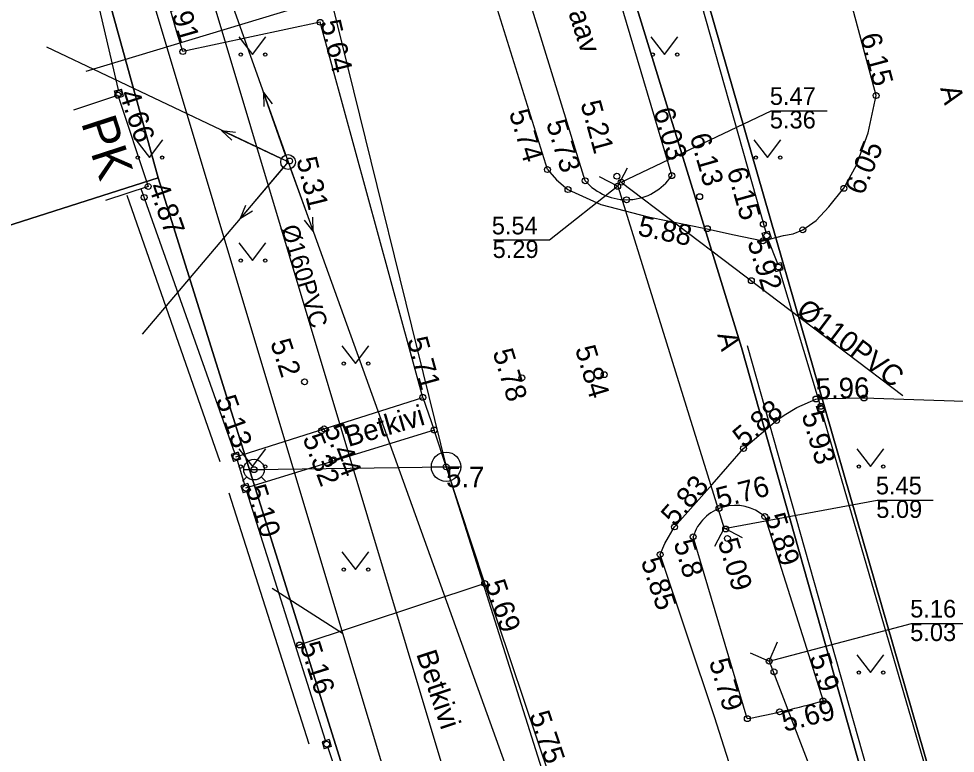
# Model space of a CAD drawing. Extents: x 473307 to 473719, y 6532843 to 6533381.
# Drawn here: x 473371.32 to 473403.15, y 6533155.23 to 6533180.18 of the extents above; entities that cross this region are included whole.
import ezdxf

# ---------------------------------------------------------------- set-up
doc = ezdxf.new("R2010")
doc.units = 0
for name, color, linetype in [('AED', 7, 'Continuous'), ('Default', 7, 'Continuous'), ('HALJASTUS', 7, 'Continuous'), ('HOONE', 7, 'Continuous'), ('KORGUS', 7, 'Continuous'), ('KTRASS', 7, 'Continuous'), ('KTRASS_TEKST', 7, 'Continuous'), ('MPKAABEL', 7, 'Continuous'), ('MPOHULIIN', 7, 'Continuous'), ('PIIR', 7, 'Continuous'), ('POST', 7, 'Continuous'), ('SITRASS', 7, 'Continuous'), ('TEE', 7, 'Continuous'), ('TRUUP', 7, 'Continuous'), ('VEEKOGU', 7, 'Continuous'), ('VKAEV', 7, 'Continuous'), ('VTRASS', 7, 'Continuous')]:
    doc.layers.add(name, color=color, linetype=linetype)

# ---------------------------------------------------------------- blocks, each defined once
blk = doc.blocks.new('VEKAEV')
at = {"layer": 'Default'}
blk.add_line((-1, 0), (1, 0), dxfattribs=at)
blk.add_circle((0, 0), 1, dxfattribs=at)
blk = doc.blocks.new('PUPOST')
at = {"layer": 'Default'}
blk.add_circle((0, 0), 0.5, dxfattribs=at)
blk = doc.blocks.new('TORVAL')
at = {"layer": 'Default'}
blk.add_lwpolyline([(-1, -1), (0, 0), (-1, 1)], dxfattribs=at)
blk = doc.blocks.new('VARPOS')
at = {"layer": 'Default'}
for p, q in [((-0.25, 0.25), (-0.25, -0.25)), ((-0.25, 0.25), (0.25, 0.25)), ((0.25, 0.25), (0.25, -0.25)), ((-0.25, -0.25), (0.25, -0.25))]:
    blk.add_line(p, q, dxfattribs=at)
blk = doc.blocks.new('MPSUUN')
at = {"layer": 'Default'}
for p, q in [((0.5, 0), (5, 0)), ((5, 0), (4.097, -0.297)), ((5, 0), (4.098, 0.3))]:
    blk.add_line(p, q, dxfattribs=at)
blk = doc.blocks.new('MURU')
at = {"layer": 'Default'}
for p, q in [((-0.927, 1.213), (0, 0)), ((0, 0), (0.891, 1.213))]:
    blk.add_line(p, q, dxfattribs=at)
for centre in [(-0.802, 0), (0.856, 0)]:
    blk.add_circle(centre, 0.11, dxfattribs=at)
blk = doc.blocks.new('VESIIB')
at = {"layer": 'Default'}
for p, q in [((-0.7, 0), (0.7, 0)), ((-0.495, -0.495), (-0.774, -0.774)), ((0.495, -0.495), (0.774, -0.774))]:
    blk.add_line(p, q, dxfattribs=at)
blk.add_circle((0, 0), 0.7, dxfattribs=at)

msp = doc.modelspace()

# ---------------------------------------------------------------- linework, layer by layer
at = {"layer": 'AED'}
for points in [[(473385.094, 6533214.054), (473385.116, 6533213.953), (473396.709, 6533172.929)], [(473374.024, 6533180.683), (473374.7, 6533177.764)], [(473378.664, 6533165.421), (473375.484, 6533174.406)], [(473396.777, 6533172.689), (473397.106, 6533171.867)], [(473397.174, 6533171.627), (473398.558, 6533167.046)], [(473572.372, 6533059.989), (473562.796, 6533044.25), (473549.715, 6533022.819), (473547.153, 6533018.61), (473538.777, 6533017.059), (473515.614, 6533013.019), (473502.84, 6533010.765), (473486.499, 6533007.9), (473486.322, 6533008.043), (473484.734, 6533009.635), (473455.331, 6533045.745), (473429.609, 6533087.699), (473409.64, 6533128.98), (473398.626, 6533166.806)], [(473378.745, 6533165.184), (473378.993, 6533164.353)], [(473381.75, 6533155.655), (473379.07, 6533164.115)], [(473381.827, 6533155.417), (473382.842, 6533152.337)]]:
    msp.add_lwpolyline(points, dxfattribs=at)
at = {"layer": 'HALJASTUS'}
for points in [[(473378.164, 6533165.124), (473375.01, 6533174.175)], [(473381.196, 6533155.535), (473378.477, 6533164.059)]]:
    msp.add_lwpolyline(points, dxfattribs=at)
at = {"layer": 'HOONE'}
msp.add_lwpolyline([(473373.195, 6533177.09), (473374.694, 6533177.588), (473375.724, 6533174.486), (473374.276, 6533174.005)], dxfattribs=at)
at = {"layer": 'KORGUS'}
for centre in [(473381.567, 6533180.064), (473376.9, 6533179.068), (473374.694, 6533177.588), (473374.732, 6533177.643), (473400.457, 6533177.573), (473380.528, 6533175.35), (473389.288, 6533175.058), (473391.649, 6533174.832), (473393.514, 6533174.851), (473375.724, 6533174.486), (473389.987, 6533174.379), (473390.574, 6533174.68), (473391.677, 6533174.49), (473391.797, 6533174.63), (473399.364, 6533174.423), (473375.587, 6533174.114), (473394.463, 6533174.138), (473391.977, 6533174.034), (473396.626, 6533173.204), (473394.722, 6533173.05), (473396.743, 6533172.809), (473397.965, 6533173.013), (473396.619, 6533172.638), (473397.14, 6533171.747), (473396.218, 6533171.283), (473391.218, 6533168.089), (473381.036, 6533167.847), (473388.422, 6533167.981), (473385.054, 6533167.319), (473398.414, 6533167.263), (473400.045, 6533167.299), (473398.577, 6533167.013), (473398.592, 6533166.926), (473397.076, 6533166.533), (473381.615, 6533166.189), (473381.702, 6533166.252), (473385.443, 6533166.209), (473395.954, 6533165.585), (473378.706, 6533165.303), (473381.973, 6533165.166), (473382.023, 6533165.198), (473379.319, 6533164.864), (473385.845, 6533164.961), (473379.032, 6533164.234), (473395.119, 6533163.543), (473396.673, 6533163.269), (473393.608, 6533162.916), (473395.345, 6533162.846), (473394.241, 6533162.58), (473395.406, 6533162.525), (473393.12, 6533161.978), (473387.158, 6533160.995), (473380.87, 6533158.905), (473396.825, 6533158.357), (473396.987, 6533157.996), (473398.653, 6533157.003), (473397.176, 6533156.632), (473396.081, 6533156.402), (473381.788, 6533155.536)]:
    msp.add_circle(centre, 0.1, dxfattribs=at)
at = {"layer": 'KTRASS'}
msp.add_line((473372.772, 6533198.006), (473385.95, 6533153.99), dxfattribs=at)
at = {"layer": 'MPKAABEL'}
for points in [[(473390.606, 6533185.72), (473391.18, 6533184.279), (473395.886, 6533169.008), (473399.947, 6533154.634), (473401.357, 6533149.404)], [(473481.096, 6533010.082), (473475.299, 6533017.476), (473469.705, 6533025.438), (473464.809, 6533033.306), (473458.878, 6533040.236), (473452.764, 6533048.342), (473452.582, 6533049.145), (473450.829, 6533050.743), (473441.685, 6533065.704), (473432.314, 6533080.211), (473428.426, 6533086.609), (473420.464, 6533103.751), (473416.16, 6533112.695), (473415.168, 6533114.011), (473413.395, 6533118.629), (473406.551, 6533134.777), (473402.712, 6533147.764), (473401.357, 6533149.404), (473399.947, 6533154.634), (473395.886, 6533169.008), (473391.18, 6533184.279)], [(473401.357, 6533149.404), (473400.149, 6533154.69), (473396.087, 6533169.067)]]:
    msp.add_lwpolyline(points, dxfattribs=at)
at = {"layer": 'MPOHULIIN'}
for points in [[(473423.194, 6533272.897), (473391.791, 6533270.484), (473361.09, 6533267.919), (473364.229, 6533220.925), (473380.477, 6533175.317), (473396.165, 6533131.758), (473413.567, 6533083.532), (473430.968, 6533052.6), (473459.84, 6533016.944), (473493.252, 6532975.715), (473524.159, 6532957.128), (473561.498, 6532934.712), (473599.705, 6532914.54), (473648.184, 6532910.183)], [(473380.477, 6533175.317), (473372.279, 6533179.221)], [(473380.477, 6533175.317), (473375.522, 6533169.472)]]:
    msp.add_lwpolyline(points, dxfattribs=at)
at = {"layer": 'PIIR'}
for points in [[(473383.26, 6533220.83), (473372.23, 6533259.41), (473496.37, 6533266.79), (473499.84, 6533206.38), (473559.2, 6533209.37), (473561.43, 6533165.2), (473601.75, 6533167.04), (473607.56, 6533132.38), (473611.09, 6533109.85), (473618.6, 6533063.82), (473572.63, 6533056.43), (473548.5, 6533028.91), (473478.82, 6533017), (473455.33, 6533045.76), (473432.18, 6533083.36), (473429.59, 6533087.74), (473409.64, 6533129), (473385.1, 6533214.25), (473398.68, 6533216.8), (473398.11, 6533224.3)], [(473340.14, 6533188.91), (473369.76, 6533197.52), (473376.06, 6533174.78), (473346.69, 6533165.4)], [(473354.12, 6533141.93), (473346.69, 6533165.4), (473376.06, 6533174.78), (473383.02, 6533152.56)]]:
    msp.add_lwpolyline(points, close=True, dxfattribs=at)
for points in [[(473385.1, 6533214.25), (473409.64, 6533129), (473429.59, 6533087.74), (473432.18, 6533083.36), (473455.33, 6533045.76), (473478.82, 6533017)], [(473492.55, 6532977.62), (473473.12, 6532997.79), (473458.1, 6533015.44), (473444.45, 6533033.74), (473430.52, 6533052.35), (473416.35, 6533075.22), (473412.06, 6533083.41), (473400.27, 6533108.71), (473390.77, 6533130.51), (473383.02, 6533152.56), (473376.06, 6533174.78), (473369.76, 6533197.52)]]:
    msp.add_lwpolyline(points, dxfattribs=at)
at = {"layer": 'SITRASS'}
msp.add_line((473379.94, 6533160.84), (473382.33, 6533159.31), dxfattribs=at)
msp.add_lwpolyline([(473373.611, 6533188.362), (473382.33, 6533159.31), (473384.49, 6533152.12), (473388.46, 6533141.59), (473398.2, 6533115.64), (473410.45, 6533090.654)], dxfattribs=at)
at = {"layer": 'TEE'}
for points in [[(473389.288, 6533175.058), (473386.342, 6533184.497), (473383.331, 6533195.545), (473380.311, 6533206.557), (473378.498, 6533213.595), (473374.322, 6533231.912), (473372.811, 6533239.717), (473371.569, 6533247.124), (473369.925, 6533258.783), (473369.534, 6533265.185), (473369.578, 6533267.313), (473370.291, 6533268.076)], [(473385.054, 6533167.319), (473384.343, 6533169.917), (473381.567, 6533180.064), (473376.9, 6533179.068), (473376.697, 6533179.729), (473376.308, 6533181.087), (473378.066, 6533181.865), (473380.843, 6533183.017), (473376.261, 6533199.603), (473372.435, 6533198.701), (473370.061, 6533197.945), (473369.268, 6533199.975), (473370.832, 6533200.741), (473375.655, 6533202.096), (473373.105, 6533212.25), (473371.642, 6533218.64)], [(473389.288, 6533175.058), (473389.596, 6533174.705), (473389.987, 6533174.379), (473391.105, 6533173.871), (473392.716, 6533173.455), (473394.722, 6533173.05), (473395.579, 6533172.853), (473396.619, 6533172.638), (473397.307, 6533172.815), (473397.644, 6533172.878), (473397.965, 6533173.013), (473398.418, 6533173.324), (473398.855, 6533173.789), (473399.364, 6533174.423), (473399.789, 6533175.214), (473400.19, 6533176.306), (473400.457, 6533177.573), (473397, 6533190.419)], [(473378.706, 6533165.303), (473385.054, 6533167.319), (473385.443, 6533166.209), (473379.032, 6533164.234)], [(473393.12, 6533161.978), (473393.28, 6533162.35), (473393.608, 6533162.916), (473394.883, 6533164.355), (473395.954, 6533165.585), (473397.076, 6533166.533), (473397.331, 6533166.714), (473397.763, 6533166.972), (473398.414, 6533167.263), (473398.812, 6533167.281), (473400.045, 6533167.299), (473410.252, 6533166.959), (473428.231, 6533166.83), (473444.41, 6533166.476)], [(473387.158, 6533160.995), (473385.443, 6533166.209)], [(473486.74, 6533007.668), (473486.486, 6533007.568), (473485.836, 6533006.833), (473483.72, 6533004.961), (473480.798, 6533008.092), (473475.573, 6533014.142), (473470.165, 6533020.489), (473464.659, 6533026.983), (473458.607, 6533034.554), (473452.151, 6533042.899), (473444.547, 6533053.352), (473438.634, 6533062.682), (473435.33, 6533068.051), (473426.278, 6533084.212), (473422.195, 6533091.615), (473414.542, 6533107.225), (473409.577, 6533117.788), (473405.358, 6533127.822), (473401.846, 6533136.79), (473397.087, 6533149.814), (473394.968, 6533156.469), (473393.12, 6533161.978)], [(473382.951, 6533152.121), (473389.399, 6533154.356), (473387.158, 6533160.995), (473380.735, 6533158.86)]]:
    msp.add_lwpolyline(points, dxfattribs=at)
at = {"layer": 'TRUUP'}
for points in [[(473391.797, 6533174.63), (473396.894, 6533177.057), (473398.797, 6533177.057)], [(473391.677, 6533174.49), (473389.364, 6533172.656), (473387.461, 6533172.656)], [(473391.677, 6533174.49), (473395.296, 6533162.867)], [(473391.797, 6533174.63), (473401.364, 6533167.385)], [(473395.296, 6533162.867), (473400.498, 6533163.823), (473402.401, 6533163.823)], [(473396.825, 6533158.357), (473401.664, 6533159.639), (473403.568, 6533159.639)], [(473396.825, 6533158.357), (473398.373, 6533154.317), (473401.733, 6533143.604)]]:
    msp.add_lwpolyline(points, dxfattribs=at)
at = {"layer": 'VEEKOGU'}
for points in [[(473390.574, 6533174.68), (473387.416, 6533184.931), (473384.324, 6533195.773), (473381.494, 6533206.54), (473379.971, 6533212.095)], [(473382.394, 6533212.218), (473384.053, 6533207.354), (473387.031, 6533196.486), (473390.326, 6533185.611), (473393.514, 6533174.851)], [(473396.673, 6533163.269), (473398.653, 6533157.003)], [(473396.081, 6533156.402), (473394.241, 6533162.58)]]:
    msp.add_lwpolyline(points, dxfattribs=at)
for centre, radius, start, end in [((473391.979, 6533175.885), 1.851, 220.6123, 326.0452), ((473395.675, 6533162.154), 1.496, 48.1747, 163.4608), ((473389.677, 6533189.612), 33.821, 280.9145, 285.3902)]:
    msp.add_arc(centre, radius, start, end, dxfattribs=at)
at = {"layer": 'VTRASS'}
for p, q in [((473373.615, 6533178.405), (473381.92, 6533180.915)), ((473379.319, 6533164.864), (473385.845, 6533164.961))]:
    msp.add_line(p, q, dxfattribs=at)
msp.add_lwpolyline([(473365.999, 6533272.186), (473364.518, 6533257.871), (473366.737, 6533240.392), (473372.861, 6533211.206), (473381.92, 6533180.915), (473385.845, 6533164.961), (473390.472, 6533150.34), (473401.875, 6533121.622), (473409.867, 6533103.775), (473420.281, 6533084.249), (473435.442, 6533057.262), (473447.562, 6533040.443), (473454.221, 6533030.196), (473471.046, 6533010.477), (473501.071, 6532979.442)], dxfattribs=at)

# ---------------------------------------------------------------- block references
at = {"layer": 'AED'}
for p, xscale, yscale, rotation in [((473374.732, 6533177.643), 0.5000000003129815, 0.5, 105.2342164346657), ((473396.743, 6533172.809), 0.49999999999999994, 0.5000000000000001, 105.86118865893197), ((473397.14, 6533171.747), 0.49999999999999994, 0.5000000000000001, 105.86118865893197), ((473398.592, 6533166.926), 0.49999999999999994, 0.5000000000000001, 105.86118865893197), ((473378.706, 6533165.303), 0.5000000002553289, 0.5000000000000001, -71.90293522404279), ((473379.032, 6533164.234), 0.5000000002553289, 0.5000000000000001, -71.90293522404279), ((473381.788, 6533155.536), 0.5000000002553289, 0.5000000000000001, -71.90293522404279)]:
    msp.add_blockref('VARPOS', p, dxfattribs=dict(at, xscale=xscale, yscale=yscale, rotation=rotation))
at = {"layer": 'HALJASTUS', "xscale": 0.5, "yscale": 0.5}
for p in [(473379.271, 6533178.967), (473393.271, 6533178.967), (473375.771, 6533175.467), (473396.771, 6533175.467), (473379.271, 6533171.967), (473382.771, 6533168.467), (473379.271, 6533164.967), (473400.271, 6533164.967), (473382.771, 6533161.467), (473400.271, 6533157.967)]:
    msp.add_blockref('MURU', p, dxfattribs=at)
at = {"layer": 'MPOHULIIN'}
for xscale, yscale, rotation in [(0.5000000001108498, 0.5, 109.54699970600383), (0.5000000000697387, 0.5, 154.535887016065), (0.5000000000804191, 0.4999999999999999, -130.2883867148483), (0.5000000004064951, 0.5, -70.19362488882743)]:
    msp.add_blockref('MPSUUN', (473380.477, 6533175.317), dxfattribs=dict(at, xscale=xscale, yscale=yscale, rotation=rotation))
at = {"layer": 'POST', "xscale": 0.5, "yscale": 0.5}
msp.add_blockref('PUPOST', (473380.477, 6533175.317), dxfattribs=at)
at = {"layer": 'TRUUP'}
for p, xscale, yscale, rotation in [((473391.677, 6533174.49), 0.5, 0.5, -72.70389997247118), ((473395.296, 6533162.873), 0.49999999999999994, 0.5000000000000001, 107.29610002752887), ((473396.825, 6533158.357), 0.4999999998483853, 0.5, -68.12332292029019)]:
    msp.add_blockref('TORVAL', p, dxfattribs=dict(at, xscale=xscale, yscale=yscale, rotation=rotation))
at = {"layer": 'VKAEV', "xscale": 0.5, "yscale": 0.5}
for name, p in [('VEKAEV', (473385.845, 6533164.961)), ('VESIIB', (473379.319, 6533164.864))]:
    msp.add_blockref(name, p, dxfattribs=at)

# ---------------------------------------------------------------- texts
at = {"layer": 'HOONE'}
msp.add_text('PK', height=1.2, rotation=288.0149, dxfattribs=at).set_placement((473373.433, 6533176.658))
at = {"layer": 'KORGUS'}
for s, rotation, p in [('4.91', 285.9845, (473376.308, 6533181.087)), ('5.64', 283.705, (473381.567, 6533180.064)), ('6.15', 285.0645, (473399.911, 6533179.601)), ('4.66', 288.3823, (473374.732, 6533177.643)), ('5.21', 285.4115, (473390.406, 6533177.308)), ('5.74', 286.6533, (473387.977, 6533176.997)), ('6.03', 285.7197, (473392.891, 6533177.065)), ('5.73', 287.1224, (473389.238, 6533176.64)), ('6.13', 286.0167, (473394.117, 6533176.189)), ('6.05', 67.5031, (473400.011, 6533174.155)), ('5.31', 283.705, (473380.755, 6533175.405)), ('6.15', 285.8032, (473395.381, 6533175.034)), ('4.87', 289.4934, (473375.724, 6533174.486)), ('5.88', 348.3741, (473392.328, 6533172.828)), ('5.92', 287.4477, (473396.075, 6533172.599)), ('5.71', 285.3015, (473384.517, 6533169.28)), ('5.2', 288.0776, (473379.864, 6533169.182)), ('5.84', 286.6913, (473390.222, 6533168.974)), ('5.78', 287.0449, (473387.421, 6533168.859)), ('5.96', 1.2809, (473398.414, 6533167.263)), ('5.13', 289.6323, (473378.012, 6533167.25)), ('5.88', 40.1951, (473395.954, 6533165.585)), ('5.93', 286.2329, (473397.92, 6533166.73)), ('5.44', 291, (473381.693, 6533166.261)), ('5.32', 290.8294, (473380.961, 6533165.94)), ('5.83', 48.6298, (473393.608, 6533162.916)), ('5.76', 14.5342, (473395.119, 6533163.543)), ('5.10', 287.581, (473379.032, 6533164.234)), ('5.89', 287.5361, (473396.673, 6533163.269)), ('5.8', 286.5852, (473393.57, 6533162.38)), ('5.09', 286.979, (473395.071, 6533162.423)), ('5.85', 288.5441, (473392.456, 6533161.755)), ('5.69', 288.6522, (473387.158, 6533160.995)), ('5.16', 287.581, (473380.87, 6533158.905)), ('5.9', 287.5361, (473398.181, 6533158.497)), ('5.79', 286.5852, (473394.773, 6533158.343)), ('5.69', 14.1001, (473397.347, 6533155.953)), ('5.75', 288.6522, (473388.663, 6533156.535))]:
    msp.add_text(s, height=0.7, rotation=rotation, dxfattribs=at).set_placement(p)
msp.add_text('5.7', height=0.7, dxfattribs=at).set_placement((473385.845, 6533164.261))
at = {"layer": 'KTRASS_TEKST'}
msp.add_text('%%c160PVC', height=0.6, rotation=286.6796, dxfattribs=at).set_placement((473380.229, 6533173.084))
at = {"layer": 'TEE'}
for s, rotation, p in [('A', 285.0645, (473402.629, 6533177.825)), ('A', 284.3181, (473395.054, 6533169.457)), ('Betkivi', 16.2968, (473382.524, 6533165.631)), ('Betkivi', 288.3956, (473384.823, 6533158.601))]:
    msp.add_text(s, height=0.7, rotation=rotation, dxfattribs=at).set_placement(p)
at = {"layer": 'TRUUP'}
for s, p in [('5.47', (473396.846, 6533177.257)), ('5.36', (473396.846, 6533176.457)), ('5.54', (473387.399, 6533172.856)), ('5.29', (473387.427, 6533172.056)), ('5.45', (473400.449, 6533164.023)), ('5.09', (473400.463, 6533163.223)), ('5.16', (473401.616, 6533159.839)), ('5.03', (473401.616, 6533159.039))]:
    msp.add_text(s, height=0.6, dxfattribs=at).set_placement(p)
msp.add_text('%%c110PVC', height=0.7, rotation=322.861, dxfattribs=at).set_placement((473397.695, 6533170.164))
at = {"layer": 'VEEKOGU'}
msp.add_text('Kraav', height=0.7, rotation=287.7316, dxfattribs=at).set_placement((473389.71, 6533181.281))

doc.saveas('drawing.dxf')
